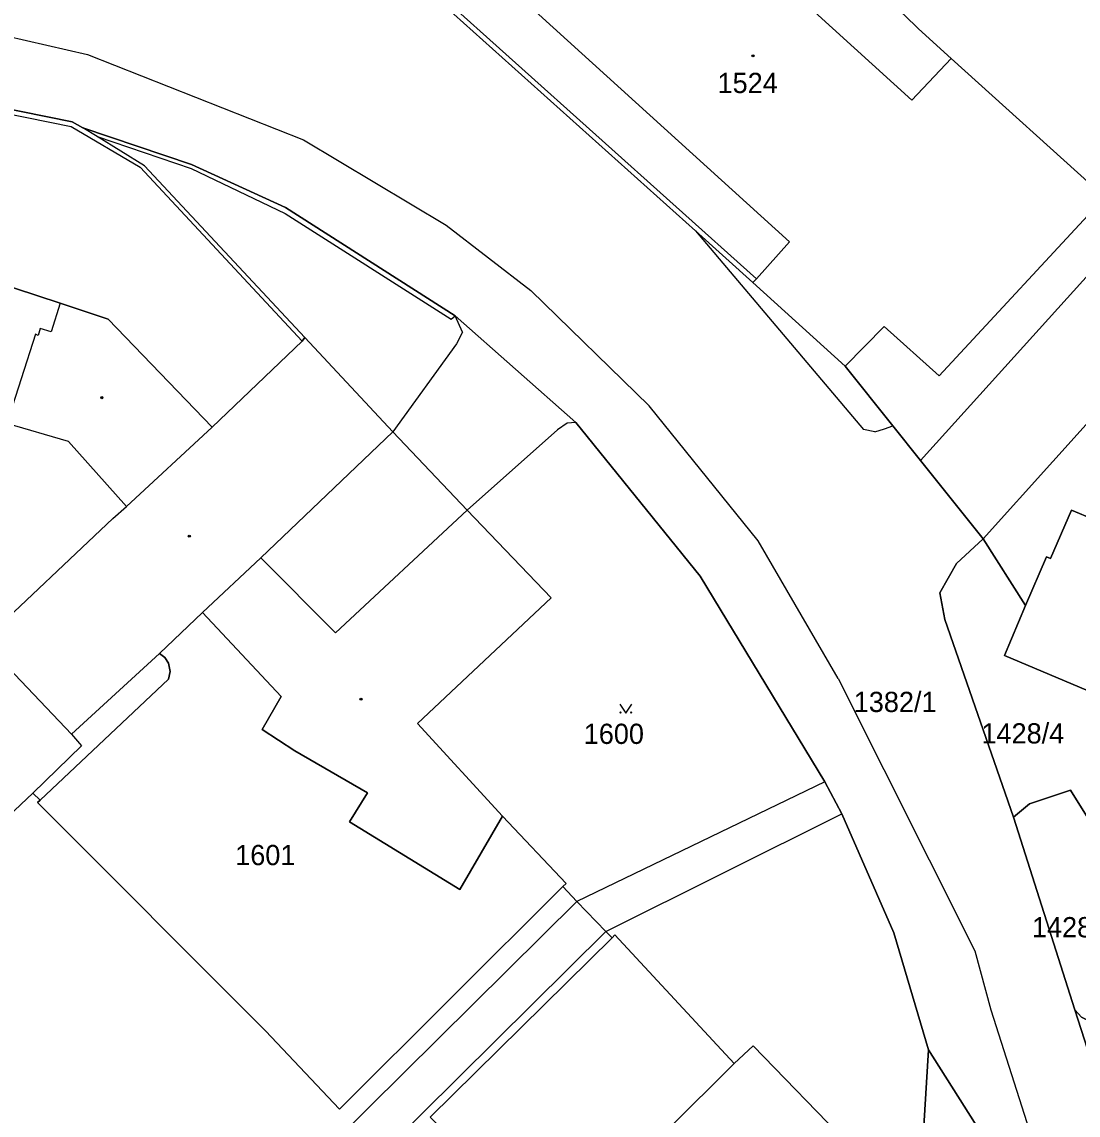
# Model space of a CAD drawing. Extents: x -598934 to -598196, y -1162208 to -1161502.
# Drawn here: x -598774.9 to -598686.2, y -1161641.4 to -1161549.6 of the extents above; entities that cross this region are included whole.
import ezdxf

# ---------------------------------------------------------------- set-up
doc = ezdxf.new("R2010")
doc.units = 0
for name, color, linetype in [('KN_CAR_KR', 7, 'Continuous'), ('KN_KULTURY', 7, 'Continuous'), ('KN_PARC_CIS_POZ', 7, 'Continuous'), ('KN_PARC_CIS_STAV', 7, 'Continuous'), ('KN_PARC_PLOCHA', 7, 'Continuous'), ('parcely_l', 7, 'Continuous')]:
    doc.layers.add(name, color=color, linetype=linetype)

msp = doc.modelspace()

# ---------------------------------------------------------------- linework, layer by layer
at = {"layer": 'KN_CAR_KR'}
for points in [[(-598626.049, -1161505.182), (-598699.41, -1161586.46)], [(-598694.17, -1161593.02), (-598615.083, -1161505.182)], [(-598719.81, -1161538.29), (-598700.16, -1161556.18)], [(-598713.19, -1161571.18), (-598746.92, -1161540.94)], [(-598781.32, -1161549.62), (-598769.35, -1161552.36)], [(-598769.35, -1161552.36), (-598751.23, -1161559.52)], [(-598700.16, -1161556.18), (-598696.84, -1161552.69)], [(-598786.06, -1161555.3), (-598770.72, -1161558.4)], [(-598770.72, -1161558.4), (-598764.92, -1161561.81)], [(-598768.55, -1161559.24), (-598769.75, -1161558.5)], [(-598768.55, -1161559.24), (-598760.64, -1161561.92)], [(-598764.58, -1161561.7), (-598768.55, -1161559.24)], [(-598751.23, -1161559.52), (-598739.24, -1161566.69)], [(-598764.92, -1161561.81), (-598751.34, -1161576.43)], [(-598751.1, -1161576.11), (-598764.58, -1161561.7)], [(-598760.64, -1161561.92), (-598752.76, -1161565.7)], [(-598752.76, -1161565.7), (-598738.82, -1161574.58)], [(-598739.24, -1161566.69), (-598732.13, -1161572.18)], [(-598718.31, -1161567.16), (-598704.2, -1161583.83)], [(-598732.13, -1161572.18), (-598722.19, -1161581.87)], [(-598771.64, -1161573.23), (-598772.41, -1161575.64)], [(-598738.82, -1161574.58), (-598738.48, -1161574.29)], [(-598737.86, -1161575.67), (-598738.48, -1161574.29)], [(-598773.33, -1161575.35), (-598773.51, -1161575.96)], [(-598772.41, -1161575.64), (-598773.33, -1161575.35)], [(-598773.73, -1161575.85), (-598776.12, -1161583.35)], [(-598773.51, -1161575.96), (-598773.73, -1161575.85)], [(-598737.86, -1161575.67), (-598738.39, -1161576.65)], [(-598738.39, -1161576.65), (-598743.71, -1161584.04)], [(-598713.05, -1161593.2), (-598722.19, -1161581.87)], [(-598770.95, -1161584.84), (-598776.12, -1161583.35)], [(-598729.09, -1161583.31), (-598729.89, -1161583.88)], [(-598728.35, -1161583.25), (-598729.09, -1161583.31)], [(-598702.45, -1161583.78), (-598701.74, -1161583.54)], [(-598758.9, -1161583.64), (-598766.07, -1161590.3)], [(-598743.71, -1161584.04), (-598754.81, -1161594.61)], [(-598729.89, -1161583.88), (-598737.49, -1161590.63)], [(-598703.26, -1161584.04), (-598704.2, -1161583.83)], [(-598703.26, -1161584.04), (-598702.45, -1161583.78)], [(-598766.07, -1161590.3), (-598770.95, -1161584.84)], [(-598767.23, -1161591.33), (-598766.07, -1161590.3)], [(-598748.53, -1161600.93), (-598737.49, -1161590.63)], [(-598767.23, -1161591.33), (-598778.14, -1161601.63)], [(-598706.33, -1161604.76), (-598713.05, -1161593.2)], [(-598754.81, -1161594.61), (-598759.71, -1161599.2)], [(-598754.81, -1161594.61), (-598748.53, -1161600.93)], [(-598778.14, -1161601.63), (-598770.71, -1161609.42)], [(-598763.32, -1161602.65), (-598770.71, -1161609.42)], [(-598706.33, -1161604.76), (-598694.86, -1161627.62)], [(-598770.71, -1161609.42), (-598769.87, -1161610.42)], [(-598769.87, -1161610.42), (-598773.95, -1161614.39)], [(-598707.45, -1161613.42), (-598728.27, -1161623.48)], [(-598725.84, -1161626), (-598706.02, -1161616.11)], [(-598774.83, -1161669.62), (-598728.27, -1161623.48)], [(-598725.84, -1161626), (-598772.17, -1161671.95)], [(-598694.86, -1161627.62), (-598693.51, -1161632.59)], [(-598693.51, -1161632.59), (-598687.48, -1161651.51)], [(-598720.61, -1161642.61), (-598715.07, -1161637.08)]]:
    msp.add_lwpolyline(points, dxfattribs=at)
at = {"layer": 'KN_KULTURY'}
msp.add_lwpolyline([(-598724.662, -1161606.912), (-598724.162, -1161607.662), (-598723.662, -1161606.912)], dxfattribs=at)
for centre, radius in [((-598713.49, -1161552.47), 0.09), ((-598713.49, -1161552.47), 0.0398), ((-598768.15, -1161581.17), 0.09), ((-598768.15, -1161581.17), 0.0398), ((-598760.81, -1161592.8), 0.09), ((-598760.81, -1161592.8), 0.0398), ((-598746.4, -1161606.49), 0.09), ((-598746.4, -1161606.49), 0.0398), ((-598724.612, -1161607.611), 0.05), ((-598723.713, -1161607.611), 0.05)]:
    msp.add_circle(centre, radius, dxfattribs=at)
at = {"layer": 'KN_PARC_PLOCHA'}
for points in [[(-598775.51, -1161540.82), (-598772.55, -1161541.22), (-598764.79, -1161543.19), (-598757.19, -1161545.72), (-598751.7, -1161547.91), (-598751.4, -1161547.24), (-598748.98, -1161544.17), (-598748.97, -1161543.41), (-598748.71, -1161542.44), (-598748.19, -1161541.59), (-598747.54, -1161540.94), (-598718.31, -1161567.16), (-598713.5, -1161571.51), (-598705.75, -1161578.52), (-598701.74, -1161583.54), (-598699.41, -1161586.46), (-598694.17, -1161593.02), (-598696.41, -1161595.1), (-598697.8, -1161597.55), (-598697.38, -1161599.8), (-598691.61, -1161616.39), (-598686.46, -1161632.58), (-598684.05, -1161640.04)], [(-598732.68, -1161547.89), (-598710.43, -1161568.09), (-598713.19, -1161571.18), (-598713.5, -1161571.51), (-598718.31, -1161567.16), (-598747.54, -1161540.94)], [(-598700.78, -1161549.06), (-598699.58, -1161550.19), (-598696.84, -1161552.69), (-598683.96, -1161564.33), (-598697.85, -1161579.33), (-598702.46, -1161575.2), (-598705.75, -1161578.52), (-598713.5, -1161571.51), (-598713.19, -1161571.18), (-598710.43, -1161568.09), (-598732.68, -1161547.89)], [(-598683.96, -1161564.33), (-598696.84, -1161552.69), (-598699.58, -1161550.19), (-598700.78, -1161549.06)], [(-598786.01, -1161554.9), (-598770.64, -1161558.01), (-598769.75, -1161558.5), (-598760.62, -1161561.58), (-598752.72, -1161565.21), (-598738.48, -1161574.29), (-598728.35, -1161583.25), (-598717.91, -1161596.16), (-598707.45, -1161613.42), (-598706.02, -1161616.11), (-598701.67, -1161626.11), (-598698.75, -1161635.93), (-598699.14, -1161642.35)], [(-598692.75, -1161645.4), (-598698.75, -1161635.93), (-598701.67, -1161626.11), (-598706.02, -1161616.11), (-598707.45, -1161613.42), (-598717.91, -1161596.16), (-598728.35, -1161583.25), (-598738.48, -1161574.29), (-598752.72, -1161565.21), (-598760.62, -1161561.58), (-598769.75, -1161558.5), (-598770.64, -1161558.01), (-598786.01, -1161554.9)], [(-598684.88, -1161591.39), (-598686.75, -1161590.63), (-598688.51, -1161594.67), (-598688.85, -1161594.54), (-598690.61, -1161598.63), (-598694.17, -1161593.02), (-598699.41, -1161586.46), (-598701.74, -1161583.54), (-598705.75, -1161578.52), (-598702.46, -1161575.2), (-598697.85, -1161579.33), (-598683.96, -1161564.33)], [(-598705.45, -1161643.89), (-598713.46, -1161635.61), (-598715.07, -1161637.08), (-598725.09, -1161626.29), (-598725.32, -1161626.54), (-598725.84, -1161626), (-598728.27, -1161623.48), (-598729.46, -1161622.23), (-598729.17, -1161621.96), (-598734.51, -1161616.31), (-598741.65, -1161608.53), (-598730.43, -1161597.98), (-598737.49, -1161590.63), (-598743.71, -1161584.04), (-598751.1, -1161576.11), (-598751.34, -1161576.43), (-598758.9, -1161583.64), (-598767.62, -1161574.57), (-598771.64, -1161573.23), (-598788.8, -1161567.6)], [(-598788.8, -1161567.6), (-598771.64, -1161573.23), (-598767.62, -1161574.57), (-598758.9, -1161583.64), (-598751.34, -1161576.43), (-598751.1, -1161576.11), (-598743.71, -1161584.04), (-598737.49, -1161590.63), (-598730.43, -1161597.98), (-598741.65, -1161608.53), (-598734.51, -1161616.31), (-598738.09, -1161622.48), (-598747.35, -1161616.79), (-598745.86, -1161614.35), (-598751.96, -1161610.84), (-598754.69, -1161609.05), (-598753.1, -1161606.27), (-598759.71, -1161599.2), (-598763.32, -1161602.65), (-598762.87, -1161603), (-598762.55, -1161603.48), (-598762.42, -1161604.18), (-598762.56, -1161604.82), (-598773.32, -1161614.96), (-598773.95, -1161614.39), (-598778.06, -1161618.24)], [(-598679.77, -1161625.44), (-598686.84, -1161614.14), (-598690.27, -1161615.29), (-598691.61, -1161616.39), (-598697.38, -1161599.8), (-598697.8, -1161597.55), (-598696.41, -1161595.1), (-598694.17, -1161593.02), (-598690.61, -1161598.63), (-598692.38, -1161602.82), (-598681.03, -1161607.6)], [(-598778.06, -1161618.24), (-598773.95, -1161614.39), (-598773.32, -1161614.96), (-598773.55, -1161615.18), (-598754.4, -1161634.33), (-598748.19, -1161640.93), (-598729.46, -1161622.23), (-598728.27, -1161623.48), (-598725.84, -1161626), (-598725.32, -1161626.54), (-598740.59, -1161641.59)], [(-598684.05, -1161640.04), (-598686.46, -1161632.58), (-598685.91, -1161633.19)], [(-598699.14, -1161642.35), (-598698.75, -1161635.93), (-598692.75, -1161645.4)]]:
    msp.add_lwpolyline(points, dxfattribs=at)
for points in [[(-598667.88, -1161588.18), (-598669.52, -1161592.02), (-598670.03, -1161591.86), (-598671.04, -1161594.18), (-598671.17, -1161594.13), (-598672.38, -1161596.98), (-598671.47, -1161597.36), (-598671.2, -1161596.71), (-598668.44, -1161597.84), (-598669.72, -1161600.81), (-598671.49, -1161604.98), (-598671.9, -1161604.81), (-598674.11, -1161610.1), (-598680.91, -1161607.31), (-598681.03, -1161607.6), (-598692.38, -1161602.82), (-598690.61, -1161598.63), (-598688.85, -1161594.54), (-598688.51, -1161594.67), (-598686.75, -1161590.63), (-598684.88, -1161591.39), (-598681.08, -1161582.58), (-598681.01, -1161582.51)], [(-598734.51, -1161616.31), (-598729.17, -1161621.96), (-598729.46, -1161622.23), (-598748.19, -1161640.93), (-598754.4, -1161634.33), (-598773.55, -1161615.18), (-598773.32, -1161614.96), (-598762.56, -1161604.82), (-598762.42, -1161604.18), (-598762.55, -1161603.48), (-598762.87, -1161603), (-598763.32, -1161602.65), (-598759.71, -1161599.2), (-598753.1, -1161606.27), (-598754.69, -1161609.05), (-598751.96, -1161610.84), (-598745.86, -1161614.35), (-598747.35, -1161616.79), (-598738.09, -1161622.48)], [(-598686.46, -1161632.58), (-598691.61, -1161616.39), (-598690.27, -1161615.29), (-598686.84, -1161614.14), (-598679.77, -1161625.44), (-598677.87, -1161630.65), (-598678.45, -1161631.7), (-598682.9, -1161633.47), (-598684.05, -1161633.8), (-598685.15, -1161633.6), (-598685.91, -1161633.19)], [(-598705.45, -1161643.89), (-598713.09, -1161651.31), (-598714.87, -1161653.1), (-598722.32, -1161660.32), (-598730.27, -1161652.14), (-598740.59, -1161641.59), (-598725.32, -1161626.54), (-598725.09, -1161626.29), (-598715.07, -1161637.08), (-598713.46, -1161635.61)]]:
    msp.add_lwpolyline(points, close=True, dxfattribs=at)
at = {"layer": 'parcely_l'}
for points in [[(-598729.85, -1161530.05), (-598734.05, -1161534.6), (-598735.16, -1161533.58), (-598736.36, -1161534.97), (-598737.49, -1161536.23), (-598736.43, -1161537.17), (-598739.51, -1161540.6), (-598732.26, -1161547.43), (-598732.68, -1161547.89), (-598710.43, -1161568.09), (-598713.19, -1161571.18), (-598713.5, -1161571.51)], [(-598683.96, -1161564.33), (-598696.84, -1161552.69), (-598699.58, -1161550.19), (-598700.78, -1161549.06), (-598703.25, -1161546.81), (-598704.54, -1161545.68), (-598708.07, -1161542.47), (-598709.35, -1161541.28), (-598711.73, -1161539.15), (-598712.96, -1161537.99), (-598719.21, -1161532.36), (-598721.34, -1161534.81), (-598722.74, -1161536.38), (-598725.82, -1161533.64), (-598724.54, -1161532.27), (-598725.04, -1161531.81)], [(-598747.54, -1161540.94), (-598718.31, -1161567.16), (-598713.5, -1161571.51)], [(-598698.75, -1161635.93), (-598701.67, -1161626.11), (-598706.02, -1161616.11), (-598707.45, -1161613.42), (-598717.91, -1161596.16), (-598728.35, -1161583.25), (-598738.48, -1161574.29), (-598752.72, -1161565.21), (-598760.62, -1161561.58), (-598769.75, -1161558.5), (-598770.64, -1161558.01), (-598786.01, -1161554.9), (-598791.02, -1161554.26), (-598794.66, -1161554.19), (-598810.2, -1161554.63), (-598810.7, -1161555.91), (-598811.54, -1161558.39), (-598813.54, -1161563.84)], [(-598814.55, -1161566.79), (-598814.3, -1161566.9), (-598812.18, -1161567.39), (-598809.94, -1161560.72), (-598807.56, -1161561.4), (-598807.18, -1161560.37), (-598807.68, -1161560.21), (-598806.32, -1161556.08), (-598801.79, -1161557.56), (-598803.17, -1161561.66), (-598803.95, -1161561.44), (-598804.35, -1161562.42), (-598788.8, -1161567.6), (-598771.64, -1161573.23), (-598767.62, -1161574.57), (-598758.9, -1161583.64), (-598751.34, -1161576.43), (-598751.1, -1161576.11), (-598743.71, -1161584.04), (-598737.49, -1161590.63), (-598730.43, -1161597.98), (-598741.65, -1161608.53), (-598734.51, -1161616.31)], [(-598705.75, -1161578.52), (-598702.46, -1161575.2), (-598697.85, -1161579.33), (-598683.96, -1161564.33)], [(-598713.5, -1161571.51), (-598705.75, -1161578.52)], [(-598705.75, -1161578.52), (-598701.74, -1161583.54), (-598699.41, -1161586.46), (-598694.17, -1161593.02)], [(-598690.61, -1161598.63), (-598688.85, -1161594.54), (-598688.51, -1161594.67), (-598686.75, -1161590.63), (-598684.88, -1161591.39), (-598681.08, -1161582.58), (-598681.01, -1161582.51)], [(-598694.17, -1161593.02), (-598696.41, -1161595.1), (-598697.8, -1161597.55), (-598697.38, -1161599.8), (-598691.61, -1161616.39)], [(-598690.61, -1161598.63), (-598694.17, -1161593.02)], [(-598773.32, -1161614.96), (-598762.56, -1161604.82), (-598762.42, -1161604.18), (-598762.55, -1161603.48), (-598762.87, -1161603), (-598763.32, -1161602.65), (-598759.71, -1161599.2), (-598753.1, -1161606.27), (-598754.69, -1161609.05), (-598751.96, -1161610.84), (-598745.86, -1161614.35), (-598747.35, -1161616.79), (-598738.09, -1161622.48), (-598734.51, -1161616.31)], [(-598681.03, -1161607.6), (-598692.38, -1161602.82), (-598690.61, -1161598.63)], [(-598773.32, -1161614.96), (-598773.95, -1161614.39), (-598778.06, -1161618.24), (-598810.91, -1161620.77)], [(-598686.46, -1161632.58), (-598685.91, -1161633.19), (-598685.15, -1161633.6), (-598684.05, -1161633.8), (-598682.9, -1161633.47), (-598678.45, -1161631.7), (-598677.87, -1161630.65), (-598679.77, -1161625.44), (-598686.84, -1161614.14), (-598690.27, -1161615.29), (-598691.61, -1161616.39)], [(-598729.46, -1161622.23), (-598748.19, -1161640.93), (-598754.4, -1161634.33), (-598773.55, -1161615.18), (-598773.32, -1161614.96)], [(-598734.51, -1161616.31), (-598729.17, -1161621.96), (-598729.46, -1161622.23)], [(-598691.61, -1161616.39), (-598686.46, -1161632.58)], [(-598725.32, -1161626.54), (-598725.84, -1161626), (-598728.27, -1161623.48), (-598729.46, -1161622.23)], [(-598740.59, -1161641.59), (-598725.32, -1161626.54)], [(-598725.32, -1161626.54), (-598725.09, -1161626.29), (-598715.07, -1161637.08), (-598713.46, -1161635.61), (-598705.45, -1161643.89)], [(-598686.46, -1161632.58), (-598684.05, -1161640.04)], [(-598701.38, -1161646.66), (-598699.14, -1161642.35), (-598698.75, -1161635.93)], [(-598692.75, -1161645.4), (-598698.75, -1161635.93)]]:
    msp.add_lwpolyline(points, dxfattribs=at)

# ---------------------------------------------------------------- texts
at = {"layer": 'KN_PARC_CIS_POZ'}
for s, p in [('1382/1', (-598705.028, -1161607.571)), ('1600', (-598727.697, -1161610.25)), ('1428/4', (-598694.307, -1161610.21)), ('1601', (-598756.957, -1161620.43)), ('1428/7', (-598690.067, -1161626.49))]:
    msp.add_text(s, height=1.7, dxfattribs=at).set_placement(p)
at = {"layer": 'KN_PARC_CIS_STAV'}
msp.add_text('1524', height=1.7, dxfattribs=at).set_placement((-598716.462, -1161555.59))

doc.saveas('drawing.dxf')
